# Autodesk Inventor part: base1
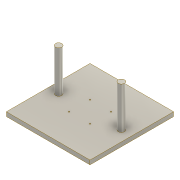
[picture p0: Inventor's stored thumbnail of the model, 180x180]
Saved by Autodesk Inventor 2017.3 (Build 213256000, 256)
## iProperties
Part Number: base1
Material: チタン
Document SubType Name: Modeling
Designer: kyushu-hep
Density: 4.51 g/cm^3
Appearance: チタン
Author: kyushu-hep
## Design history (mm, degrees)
sketch "スケッチ3"
  geometry: L1 (-100, 100)-(100, 100); L2 (100, 100)-(100, -100); L3 (100, -100)-(-100, -100); L4 (-100, -100)-(-100, 100); 1 further point
  constraints: 8 end point, 2 parallel, 1 horizontal, 1 perpendicular
  dimensions: "d19" = 100 distance from line of L1 point (0, 0); "d20" = 200 distance of L3.end L1.start; "d21" = 200 distance of L1.start L1.end; "d22" = 100 distance from line of L4 point (0, 0)
extrude "押し出し3" new body sketch "スケッチ3" distance "d23" = 10; taper "d24" = 0 deg
sketch "スケッチ4"
  geometry: C1 r 7.5 at (-75, 0); C2 r 7.5 at (75, 0); 1 further point
  constraints: 2 centre point
  dimensions: "d55" = 15 diameter of C1; "d57" = 15 diameter of C2; "d58" = 0 vertical distance of point (0, 0) C1.centre; "d59" = 75 distance of point (0, 0) C1.centre; "d62" = 0 vertical distance of point (0, 0) C2.centre; "d65" = 75 distance of C2.centre point (0, 0)
sketch "スケッチ6"
  geometry: L1 (52, -52)-(-52, -52); L2 (-52, -52)-(-52, 52); L3 (-52, 52)-(52, 52); L4 (52, 52)-(52, -52); L5 (52, -52)-(-52, 52); L6 (-52, -52)-(52, 52); C1 r 1.5 at (-25, 25); C2 r 1.5 at (25, 25); C3 r 1.5 at (-25, -25); C4 r 1.5 at (25, -25); 1 further point
  constraints: 12 end point, 4 centre point, 2 horizontal, 2 midpoint, 2 parallel, 1 perpendicular, 1 vertical, 6 other
  dimensions: "d38" = 3 diameter of C1; "d40" = 25 horizontal distance of point (0, 0) C1.centre; "d43" = 50 distance of C1.centre C2.centre; "d46" = 50 distance of C1.centre C3.centre; "d51" = 25 horizontal distance of point (0, 0) C2.centre
extrude "押し出し6" cut sketch "スケッチ6" distance "d49" = 10; taper "d50" = 0 deg
extrude "押し出し8" join sketch "スケッチ4" distance "d63" = 100; taper "d64" = 0 deg
node "ソリッド2"
